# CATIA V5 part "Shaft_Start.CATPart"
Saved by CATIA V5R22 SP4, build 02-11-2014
Part number: Shaft
Bounding box of the stored display mesh (mm): x -25 to 25, y -25 to 25, z -15 to 32
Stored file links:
  C:\DATA\Car_ASSY\教育モデル\9_EXE\Shaft_Start.CATPart
  C:\DATA\Car_ASSY\教育モデル\9_EXE\Shaft_FIN.CATPart
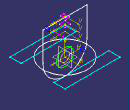
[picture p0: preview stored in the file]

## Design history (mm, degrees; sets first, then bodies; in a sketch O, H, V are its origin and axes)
Set1
  Plane1: type Offset, RefPlane xy-plane, Offset 20
  Plane2: type Offset, RefPlane Plane1, Offset 6
  Plane3: type Offset, RefPlane Plane1, Offset 12
Body1 (main body)
Body2
  Sketch1 on xy-plane, origin (0, 0, 0), H (1, 0, 0), V (0, 1, 0)
    circle A1 centre (0, 0) radius 20
    radius A1 = 20
  Sketch2 on Plane1, origin (0, 0, 20), H (1, 0, 0), V (0, 1, 0)
    line L1 (-5, 5) -> (5, 5)
    line L2 (5, 5) -> (5, -5)
    line L3 (5, -5) -> (-5, -5)
    line L4 (-5, -5) -> (-5, 5)
    length L2 = 10
    length L1 = 10
    horizontal: L1 H, L3 H
    vertical: L2 V, L4 V
    symmetry: L2 L4 V, L1 L3 H
  Sketch3 on Plane2, origin (0, 0, 26), H (1, 0, 0), V (0, 1, 0)
    construction line L1 through (0, 0) direction (1, 0)
    line L2 (-2.5, 2.5) -> (2.5, 2.5)
    line L3 (2.5, -2.5) -> (-2.5, -2.5)
    construction line L4 through (0, 0) direction (0, 1)
    line L5 (2.5, 2.5) -> (2.5, -2.5)
    line L6 (-2.5, -2.5) -> (-2.5, 2.5)
    point P1 (0, 0)
    length L5 = 5
    length L2 = 5
    horizontal: L2 L1, L3 L1
    vertical: L5 L4, L6 L4
    symmetry: L5 L6 L4, L2 L3 L1
    coincidence: L1 H, L4 V
  Sketch4 on Plane3, origin (0, 0, 32), H (1, 0, 0), V (0, 1, 0)
    construction line L1 through (0, 0) direction (1, 0)
    line L2 (-1.5, 2.5) -> (1.5, 2.5)
    line L3 (1.5, -2.5) -> (-1.5, -2.5)
    construction line L4 through (0, 0.2002) direction (0, 1)
    line L5 (1.5, 2.5) -> (1.5, -2.5)
    line L6 (-1.5, -2.5) -> (-1.5, 2.5)
    point P1 (0, 0)
    length L5 = 5
    length L2 = 3
    horizontal: L2 L1, L3 L1
    vertical: L5 L4, L6 L4
    symmetry: L5 L6 L4, L2 L3 L1
    coincidence: L1 H, L4 V
  Sketch5 on xy-plane, origin (0, 0, 0), H (1, 0, 0), V (0, 1, 0)
    line L1 (-25, 15) -> (25, 15)
    line L2 (25, 15) -> (25, 25)
    line L3 (25, 25) -> (-25, 25)
    line L4 (-25, 25) -> (-25, 15)
    line L5 (-25, -15) -> (25, -15)
    line L6 (25, -15) -> (25, -25)
    line L7 (25, -25) -> (-25, -25)
    line L8 (-25, -25) -> (-25, -15)
    distance L1 H = 15
    horizontal: L1 H, L3 H, L5 H, L7 H
    vertical: L2 V, L4 V, L6 V, L8 V
    symmetry: L1 L5 H, L6 L8 V
Body3
  Sketch6 on zx-plane, origin (0, 0, 0), H (-1, 0, 0), V (0, 0, 1)
    line L1 (-20, 31.1043) -> (-20, 5)
    arc A1 centre (0, 5) radius 20 from (-20, 5) to (20, 5) ccw
    point P3 (0, 5)
    line L2 (20, 5) -> (20, 31.1043)
    line L3 (20, 31.1043) -> (-20, 31.1043)
    radius A1 = 20
    distance P3 H = 5
    vertical: L1 V
    tangency: A1 L1, L2 A1
    horizontal: L3 H
    symmetry: L1 L2 V
Body4
  Sketch7 on zx-plane, origin (0, 0, 0), H (-1, 0, 0), V (0, 0, 1)
    circle A1 centre (0, 0) radius 7.5
    radius A1 = 7.5
  Sketch8 on zx-plane, origin (0, 0, 0), H (-1, 0, 0), V (0, 0, 1)
    circle A1 centre (0, 0) radius 4
    radius A1 = 4
Body5
  Sketch9 on yz-plane, origin (0, 0, 0), H (0, 1, 0), V (0, 0, 1)
    circle A1 centre (16, 14) radius 2
    point P1 (16, 14)
    reference intersected line E1 (-20, 20) -> (20, 20)
    reference intersected line E2 (15, -30) -> (15, 30)
    radius A1 = 2
    distance E1 P1 = 6
    distance E2 P1 = 1
  Sketch10 on yz-plane, origin (0, 0, 0), H (0, 1, 0), V (0, 0, 1)
    circle A1 centre (-16, 14) radius 2
    point P1 (-16, 14)
    reference intersected line E1 (-20, 20) -> (20, 20)
    reference intersected line E2 (-15, 30) -> (-15, -30)
    radius A1 = 2
    distance E1 P1 = 6
    distance E2 P1 = 1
